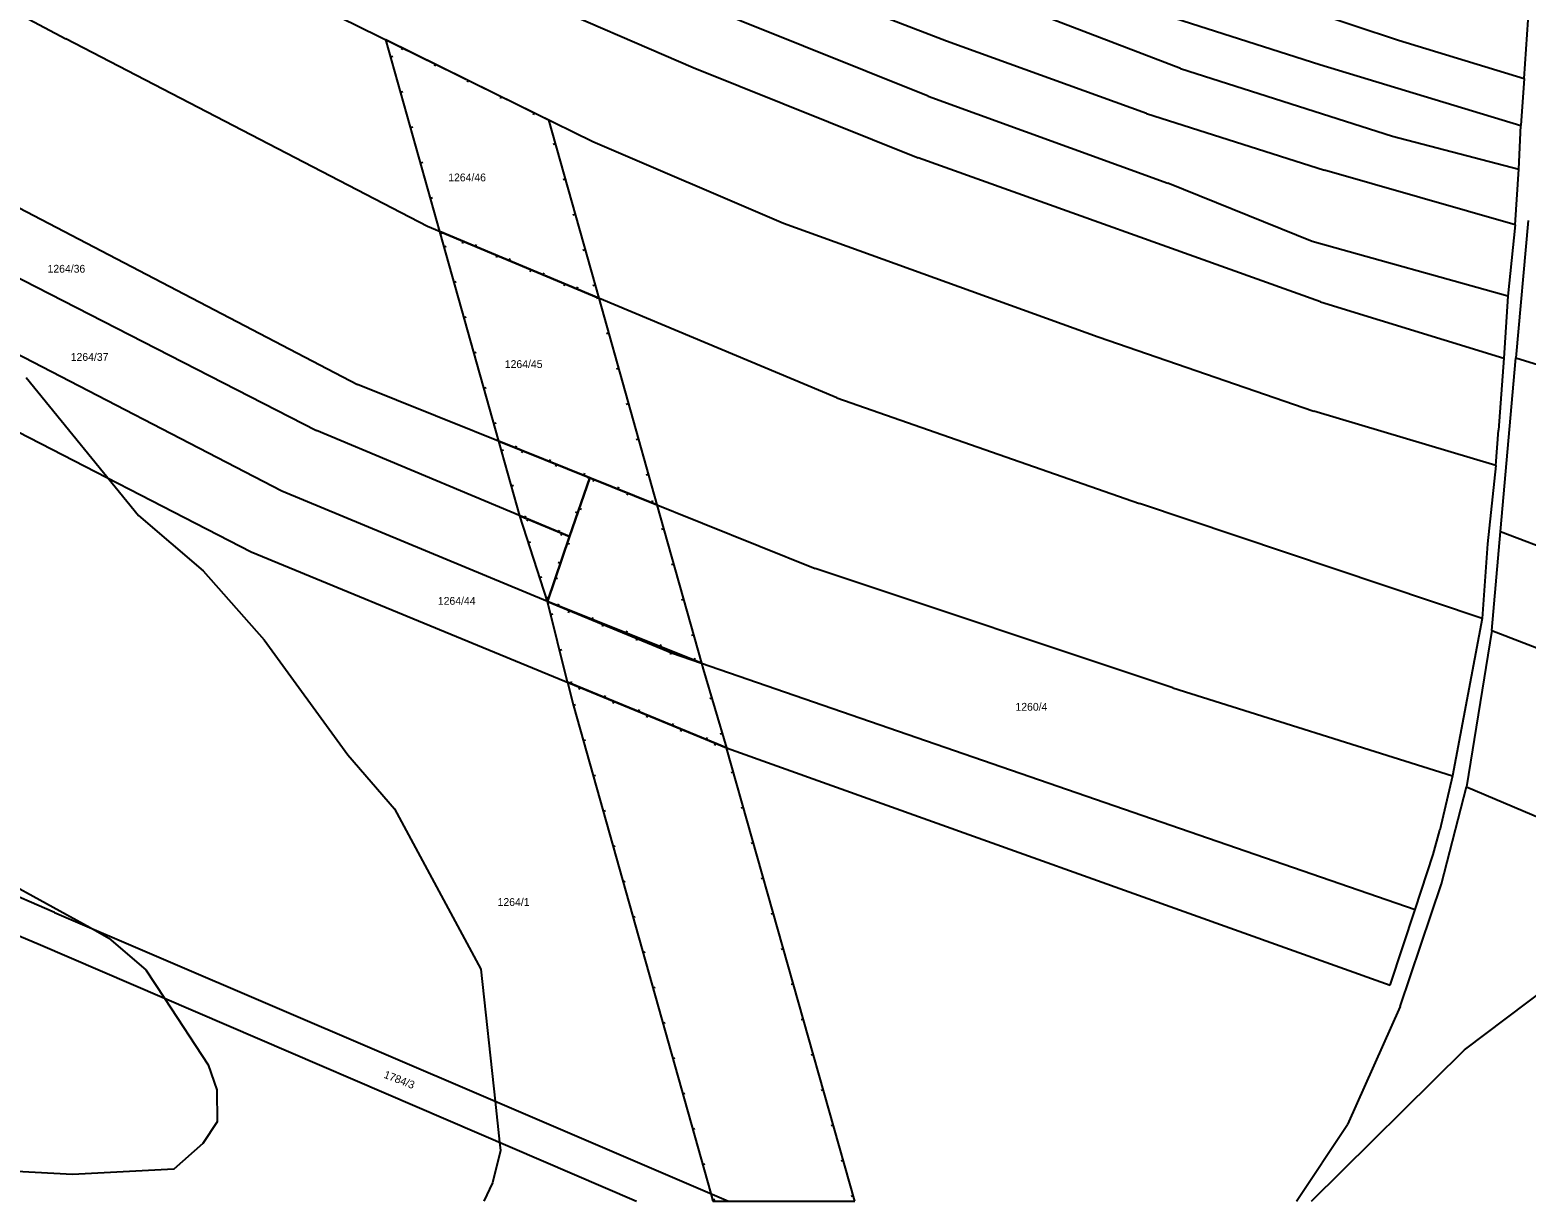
# Model space of a CAD drawing. Extents: x -779618 to -776429, y -1144546 to -1143350.
# Drawn here: x -776962 to -776635.9, y -1144546.2 to -1144290.9 of the extents above; entities that cross this region are included whole.
import ezdxf

# ---------------------------------------------------------------- set-up
doc = ezdxf.new("R2010")
doc.units = 0
for name, color, linetype in [('1', 7, 'Continuous'), ('11', 7, 'Continuous'), ('13', 7, 'Continuous'), ('2', 7, 'Continuous')]:
    doc.layers.add(name, color=color, linetype=linetype)

msp = doc.modelspace()

# ---------------------------------------------------------------- linework, layer by layer
at = {"layer": '1'}
for p, q in [((-777028.31, -1144253.56), (-776954.15, -1144292.83)), ((-776711.19, -1144299.29), (-776774.48, -1144275.05)), ((-776705.35, -1144279.29), (-776663.68, -1144293.1)), ((-776853.05, -1144283.62), (-776817.39, -1144299.09)), ((-776766.15, -1144305.37), (-776821.12, -1144283.25)), ((-776902.81, -1144283.92), (-776839.24, -1144315.25)), ((-776762.2, -1144293.37), (-776786.97, -1144283.73)), ((-776712.44, -1144288.36), (-776680.82, -1144298.45)), ((-776636.28, -1144301.51), (-776635.38, -1144288.7)), ((-776875.28, -1144333.73), (-776954.15, -1144292.83)), ((-776718.59, -1144309.15), (-776762.2, -1144293.37)), ((-776663.68, -1144293.1), (-776636.28, -1144301.51)), ((-777059.93, -1144296.08), (-776899.5, -1144378.24)), ((-776817.39, -1144299.09), (-776768.34, -1144318.75)), ((-776711.19, -1144299.29), (-776664.96, -1144314.03)), ((-776680.82, -1144298.45), (-776636.99, -1144311.7)), ((-776636.28, -1144301.51), (-776636.99, -1144311.7)), ((-776766.15, -1144305.37), (-776713.92, -1144324.31)), ((-776718.59, -1144309.15), (-776679.82, -1144321.5)), ((-776637.43, -1144321.26), (-776636.99, -1144311.7)), ((-776907.06, -1144391.45), (-777057.04, -1144313.68)), ((-776839.24, -1144315.25), (-776797.73, -1144333.05)), ((-776664.96, -1144314.03), (-776637.43, -1144321.26)), ((-776680.67, -1144350.14), (-776768.34, -1144318.75)), ((-776638.22, -1144333.36), (-776679.82, -1144321.5)), ((-776638.22, -1144333.36), (-776637.43, -1144321.26)), ((-776972.98, -1144325.14), (-776890.54, -1144368.22)), ((-776682.45, -1144337.04), (-776713.92, -1144324.31)), ((-777054.36, -1144332.29), (-776913.77, -1144404.64)), ((-776635.44, -1144332.47), (-776638.11, -1144362.4)), ((-776786.11, -1144371.1), (-776875.28, -1144333.73)), ((-776797.73, -1144333.05), (-776729.16, -1144357.79)), ((-776638.22, -1144333.36), (-776639.8, -1144348.93)), ((-776639.8, -1144348.93), (-776682.45, -1144337.04)), ((-776680.67, -1144350.14), (-776640.68, -1144362.46)), ((-776639.8, -1144348.93), (-776640.68, -1144362.46)), ((-776729.16, -1144357.79), (-776682.12, -1144373.99)), ((-776640.68, -1144362.46), (-776641.88, -1144378.18)), ((-776641.45, -1144400.26), (-776638.11, -1144362.4)), ((-776638.11, -1144362.4), (-776471.4, -1144413.28)), ((-776839.91, -1144388.52), (-776890.54, -1144368.22)), ((-776786.11, -1144371.1), (-776720.15, -1144394.15)), ((-776642.44, -1144385.83), (-776682.12, -1144373.99)), ((-776642.44, -1144385.83), (-776641.88, -1144378.18)), ((-776844.36, -1144401.36), (-776899.5, -1144378.24)), ((-776642.44, -1144385.83), (-776644.25, -1144402.96)), ((-776844.36, -1144401.36), (-776839.91, -1144388.52)), ((-776839.91, -1144388.52), (-776790.82, -1144408.29)), ((-776849.18, -1144415.53), (-776907.06, -1144391.45)), ((-776645.46, -1144419.21), (-776720.15, -1144394.15)), ((-776643.31, -1144421.84), (-776641.45, -1144400.26)), ((-776641.45, -1144400.26), (-776434.77, -1144478.67)), ((-776849.18, -1144415.53), (-776844.36, -1144401.36)), ((-776644.25, -1144402.96), (-776645.46, -1144419.21)), ((-776913.77, -1144404.64), (-776810.11, -1144447.4)), ((-776712.85, -1144434.32), (-776790.82, -1144408.29)), ((-776849.18, -1144415.53), (-776821.88, -1144426.73)), ((-776645.46, -1144419.21), (-776651.92, -1144453.52)), ((-776643.31, -1144421.84), (-776648.85, -1144455.92)), ((-776643.31, -1144421.84), (-776553.05, -1144456.51)), ((-776821.88, -1144426.73), (-776660.02, -1144482.62)), ((-776712.85, -1144434.32), (-776651.92, -1144453.52)), ((-776956.61, -1144483.27), (-777035.23, -1144449.5)), ((-776810.11, -1144447.4), (-776665.46, -1144499.1)), ((-776651.92, -1144453.52), (-776654.64, -1144465.36)), ((-776654.33, -1144477.04), (-776648.85, -1144455.92)), ((-776648.85, -1144455.92), (-776592.37, -1144479.79)), ((-777038.68, -1144457.26), (-776960.15, -1144490.15)), ((-776656.14, -1144470.67), (-776654.64, -1144465.36)), ((-776660.02, -1144482.62), (-776656.14, -1144470.67)), ((-776663.3, -1144503.79), (-776654.33, -1144477.04)), ((-776956.61, -1144483.27), (-776862.1, -1144523.76)), ((-776665.46, -1144499.1), (-776660.02, -1144482.62)), ((-776960.15, -1144490.15), (-776829.74, -1144546.2)), ((-776663.3, -1144503.79), (-776674.79, -1144529.52)), ((-776862.1, -1144523.76), (-776851.37, -1144528.36)), ((-776851.37, -1144528.36), (-776809.72, -1144546.2)), ((-776685.9, -1144546.2), (-776674.79, -1144529.52))]:
    msp.add_line(p, q, dxfattribs=at)
at = {"layer": '11'}
for points in [[(-776962.8, -1144366.65), (-776938.27, -1144396.78), (-776924.21, -1144408.81), (-776910.91, -1144423.83), (-776892.65, -1144448.94), (-776882.5, -1144460.66), (-776863.67, -1144495.65), (-776860.56, -1144524.42), (-776859.59, -1144533.37), (-776859.4, -1144535.14), (-776861.11, -1144542.25), (-776863.04, -1144546.2)], [(-776967.88, -1144476.09), (-776948.86, -1144486.59), (-776944.75, -1144488.86), (-776936.66, -1144495.82), (-776932.62, -1144501.98), (-776923.11, -1144516.5), (-776921.24, -1144521.95), (-776921.18, -1144528.94), (-776924.27, -1144533.66), (-776930.58, -1144539.26), (-776952.64, -1144540.38), (-776975.77, -1144539.15)], [(-776682.61, -1144546.2), (-776649.28, -1144513.21), (-776630.96, -1144499.43), (-776615.4, -1144493.47), (-776608.51, -1144492.06), (-776596.85, -1144492.7), (-776564.3, -1144498.71), (-776526.55, -1144513.12), (-776512.1, -1144516.1), (-776488.13, -1144513.07), (-776459.99, -1144502.69), (-776434.77, -1144497.31)]]:
    msp.add_lwpolyline(points, dxfattribs=at)
at = {"layer": '13'}
for p, q in [((-776883.34, -1144296.78), (-776882.86, -1144296.64)), ((-776880.77, -1144294.79), (-776880.99, -1144295.23)), ((-776873.59, -1144298.32), (-776873.81, -1144298.77)), ((-776866.41, -1144301.86), (-776866.64, -1144302.31)), ((-776881.17, -1144304.48), (-776880.69, -1144304.35)), ((-776859.24, -1144305.39), (-776859.46, -1144305.84)), ((-776852.06, -1144308.93), (-776852.28, -1144309.38)), ((-776879, -1144312.18), (-776878.52, -1144312.05)), ((-776847.45, -1144315.76), (-776847.93, -1144315.9)), ((-776876.84, -1144319.88), (-776876.35, -1144319.75)), ((-776845.28, -1144323.46), (-776845.76, -1144323.6)), ((-776874.67, -1144327.58), (-776874.19, -1144327.45)), ((-776843.11, -1144331.17), (-776843.59, -1144331.3)), ((-776872.5, -1144335.28), (-776872.02, -1144335.15)), ((-776871.68, -1144338.17), (-776871.2, -1144338.04)), ((-776867.55, -1144336.98), (-776867.74, -1144337.44)), ((-776864.83, -1144338.12), (-776864.63, -1144337.65)), ((-776840.94, -1144338.87), (-776841.43, -1144339)), ((-776860.17, -1144340.07), (-776860.36, -1144340.53)), ((-776857.45, -1144341.21), (-776857.26, -1144340.75)), ((-776852.79, -1144343.16), (-776852.98, -1144343.62)), ((-776850.07, -1144344.3), (-776849.88, -1144343.84)), ((-776869.51, -1144345.87), (-776869.03, -1144345.74)), ((-776845.41, -1144346.25), (-776845.61, -1144346.71)), ((-776842.69, -1144347.39), (-776842.5, -1144346.93)), ((-776838.78, -1144346.57), (-776839.26, -1144346.7)), ((-776838, -1144349.31), (-776838.48, -1144349.45)), ((-776867.35, -1144353.57), (-776866.86, -1144353.44)), ((-776835.83, -1144357.01), (-776836.31, -1144357.15)), ((-776865.18, -1144361.27), (-776864.69, -1144361.14)), ((-776833.66, -1144364.72), (-776834.14, -1144364.85)), ((-776863.01, -1144368.97), (-776862.53, -1144368.84)), ((-776831.49, -1144372.42), (-776831.98, -1144372.55)), ((-776860.84, -1144376.68), (-776860.36, -1144376.54)), ((-776829.32, -1144380.12), (-776829.81, -1144380.25)), ((-776859.18, -1144382.55), (-776858.7, -1144382.42)), ((-776856.07, -1144382.04), (-776855.88, -1144381.58)), ((-776854.63, -1144382.62), (-776854.82, -1144383.08)), ((-776848.64, -1144385.02), (-776848.46, -1144384.55)), ((-776847.21, -1144385.59), (-776847.4, -1144386.06)), ((-776841.22, -1144388), (-776841.03, -1144387.53)), ((-776827.16, -1144387.82), (-776827.64, -1144387.95)), ((-776857.01, -1144390.25), (-776856.53, -1144390.12)), ((-776839.95, -1144388.65), (-776840.43, -1144388.48)), ((-776839.05, -1144388.87), (-776839.24, -1144389.33)), ((-776833.8, -1144390.98), (-776833.61, -1144390.52)), ((-776831.63, -1144391.85), (-776831.82, -1144392.32)), ((-776826.38, -1144393.97), (-776826.19, -1144393.5)), ((-776854.09, -1144397.28), (-776853.89, -1144396.82)), ((-776853.44, -1144397.55), (-776853.63, -1144398.01)), ((-776842.57, -1144396.21), (-776843.05, -1144396.04)), ((-776842.23, -1144395.21), (-776841.75, -1144395.37)), ((-776846.71, -1144400.38), (-776846.51, -1144399.91)), ((-776846.06, -1144400.65), (-776846.25, -1144401.11)), ((-776823.81, -1144399.69), (-776824.29, -1144399.83)), ((-776853.29, -1144402.67), (-776852.82, -1144402.52)), ((-776844.84, -1144402.77), (-776844.37, -1144402.93)), ((-776846.34, -1144407.19), (-776846.82, -1144407.03)), ((-776821.64, -1144407.39), (-776822.12, -1144407.53)), ((-776850.86, -1144410.29), (-776850.38, -1144410.14)), ((-776847.41, -1144410.34), (-776846.94, -1144410.5)), ((-776848.92, -1144414.76), (-776849.39, -1144414.6)), ((-776846.84, -1144416.46), (-776846.66, -1144416)), ((-776819.47, -1144415.09), (-776819.95, -1144415.23)), ((-776848.48, -1144418.34), (-776847.99, -1144418.22)), ((-776844.46, -1144417.47), (-776844.65, -1144417.93)), ((-776839.41, -1144419.42), (-776839.22, -1144418.96)), ((-776837.06, -1144420.5), (-776837.25, -1144420.97)), ((-776831.98, -1144422.38), (-776831.79, -1144421.92)), ((-776829.66, -1144423.54), (-776829.85, -1144424)), ((-776817.3, -1144422.8), (-776817.78, -1144422.93)), ((-776846.53, -1144426.1), (-776846.05, -1144425.98)), ((-776824.54, -1144425.34), (-776824.36, -1144424.88)), ((-776822.26, -1144426.6), (-776822.43, -1144427.07)), ((-776817.11, -1144428.3), (-776816.93, -1144427.84)), ((-776844.05, -1144433.4), (-776843.86, -1144432.94)), ((-776842.15, -1144434.19), (-776842.34, -1144434.65)), ((-776836.66, -1144436.45), (-776836.47, -1144435.99)), ((-776813.32, -1144436.58), (-776813.8, -1144436.73)), ((-776843.53, -1144438.1), (-776843.04, -1144437.97)), ((-776834.75, -1144437.24), (-776834.94, -1144437.7)), ((-776829.26, -1144439.5), (-776829.07, -1144439.04)), ((-776827.35, -1144440.29), (-776827.55, -1144440.75)), ((-776821.87, -1144442.55), (-776821.68, -1144442.09)), ((-776819.96, -1144443.34), (-776820.15, -1144443.8)), ((-776841.36, -1144445.8), (-776840.88, -1144445.66)), ((-776814.47, -1144445.6), (-776814.28, -1144445.14)), ((-776812.56, -1144446.39), (-776812.75, -1144446.85)), ((-776811.04, -1144444.25), (-776811.52, -1144444.4)), ((-776808.61, -1144452.69), (-776809.09, -1144452.83)), ((-776839.19, -1144453.5), (-776838.71, -1144453.36)), ((-776837.03, -1144461.2), (-776836.54, -1144461.06)), ((-776806.44, -1144460.39), (-776806.92, -1144460.53)), ((-776834.86, -1144468.9), (-776834.38, -1144468.76)), ((-776804.26, -1144468.09), (-776804.74, -1144468.22)), ((-776802.08, -1144475.79), (-776802.56, -1144475.92)), ((-776832.69, -1144476.6), (-776832.21, -1144476.46)), ((-776830.52, -1144484.3), (-776830.04, -1144484.16)), ((-776799.91, -1144483.48), (-776800.39, -1144483.62)), ((-776828.35, -1144492), (-776827.87, -1144491.86)), ((-776797.73, -1144491.18), (-776798.21, -1144491.32)), ((-776795.55, -1144498.88), (-776796.03, -1144499.02)), ((-776826.18, -1144499.7), (-776825.7, -1144499.57)), ((-776824.01, -1144507.4), (-776823.53, -1144507.27)), ((-776793.38, -1144506.58), (-776793.86, -1144506.72)), ((-776821.85, -1144515.1), (-776821.36, -1144514.97)), ((-776791.2, -1144514.28), (-776791.68, -1144514.41)), ((-776819.68, -1144522.8), (-776819.2, -1144522.67)), ((-776789.02, -1144521.98), (-776789.5, -1144522.11)), ((-776817.51, -1144530.5), (-776817.03, -1144530.37)), ((-776786.84, -1144529.67), (-776787.33, -1144529.81)), ((-776784.67, -1144537.37), (-776785.15, -1144537.51)), ((-776815.34, -1144538.2), (-776814.86, -1144538.07)), ((-776813.17, -1144545.9), (-776812.69, -1144545.77)), ((-776813.09, -1144546.2), (-776782.17, -1144546.2)), ((-776782.49, -1144545.07), (-776782.97, -1144545.21))]:
    msp.add_line(p, q, dxfattribs=at)
for points in [[(-776848.94, -1144310.47), (-776837.99, -1144349.36), (-776872.62, -1144334.85), (-776884.41, -1144292.99)], [(-776872.62, -1144334.85), (-776837.99, -1144349.36), (-776825.3, -1144394.4), (-776839.91, -1144388.52), (-776859.74, -1144380.57)], [(-776859.74, -1144380.57), (-776839.91, -1144388.52), (-776844.36, -1144401.36), (-776855.16, -1144396.83)], [(-776825.3, -1144394.4), (-776815.58, -1144428.91), (-776849.18, -1144415.53), (-776844.36, -1144401.36), (-776839.91, -1144388.52)], [(-776849.18, -1144415.53), (-776855.16, -1144396.83), (-776844.36, -1144401.36)], [(-776815.58, -1144428.91), (-776815.2, -1144430.24), (-776810.11, -1144447.4), (-776844.78, -1144433.1), (-776849.18, -1144415.53), (-776821.88, -1144426.73)]]:
    msp.add_lwpolyline(points, close=True, dxfattribs=at)
msp.add_lwpolyline([(-776782.17, -1144546.2), (-776810.11, -1144447.4), (-776844.78, -1144433.1), (-776843.5, -1144438.21), (-776813.55, -1144544.56), (-776813.09, -1144546.2)], dxfattribs=at)

# ---------------------------------------------------------------- texts
at = {"layer": '2'}
for s, p in [('1264/46', (-776870.78, -1144323.9)), ('1264/36', (-776958.11, -1144343.81)), ('1264/37', (-776953.06, -1144363.04)), ('1264/45', (-776858.45, -1144364.59)), ('1264/44', (-776873.04, -1144416.21)), ('1260/4', (-776747.15, -1144439.3)), ('1264/1', (-776860.02, -1144481.86))]:
    msp.add_text(s, height=1.7, dxfattribs=at).set_placement(p)
msp.add_text('1784/3', height=1.7, rotation=338.7326, dxfattribs=at).set_placement((-776884.98, -1144519.27))

doc.saveas('drawing.dxf')
